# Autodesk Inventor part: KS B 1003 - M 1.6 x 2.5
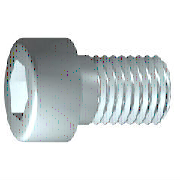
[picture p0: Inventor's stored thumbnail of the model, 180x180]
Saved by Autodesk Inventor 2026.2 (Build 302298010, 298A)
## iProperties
Created: 2025-01
Part Number: KS B 1003 - M 1.6 x 2.5
Material: 강철, 연강
Description: 6각머리 태핑 나사
Document SubType Name: Modeling
Standard: KS B 1003
Designer: khw
Standards Organization: KS
Language: ko-KR
Size Designation: M 1.6 x 2.5
Categories: <MemberInstance><Categories><Category DisplayName="조임쇠" InternalName="e4da775c-781d-43d5-af7c-5136215cf5a6" Mnemonic="FSTN"><Category DisplayName="볼트" InternalN
Density: 7.85 g/cm^3
Appearance: 반연마
IsCustomPart: 1
Author: khw
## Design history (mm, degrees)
workplane "Work Plane1"
fillet "Fillet2" dims "d30" = 0.1 (= R)
revolve "본체" stored, may be unused: angle "d10" = 90 deg
sketch "스케치2"
  geometry: L1 (0, -2.1)-(0, 2.1) reference; L2 (-2.1, 0)-(2.1, 0) reference; L3 (0.866, 0)-(0.433, -0.75); L4 (0.433, -0.75)-(-0.433, -0.75); L5 (-0.433, -0.75)-(-0.866, 0); L6 (-0.866, 0)-(-0.433, 0.75); L7 (-0.433, 0.75)-(0.433, 0.75); L8 (0.433, 0.75)-(0.866, 0); 2 further points
  constraints: 12 end point, 1 coincident, 1 horizontal alignment, 1 point on line, 12 other
extrude "슬롯" join sketch "스케치2" stored distance "d11" = 10; taper "d12" = 0 deg
body "Solid1"
fillet "모깎기1" dims "d17" = 0.16 (= RR)
feature "스레드" dims "d13" = 1.625 (= GEL), "d14" = 0
chamfer "모따기1" distance "d15" = 0.21471 (= -0.5 x SPD + 0.5 x GD); stored, may be unused: second distance "d16" = 0.21471 (= GUL), angle "d27" = 45 deg
sketch "스케치1"
  geometry: L1 (-0.4, 0)-(2.5, 0); L2 (2.5, 0)-(2.5, 0.8); L3 (2.5, 0.8)-(0.875, 0.8); L4 (0.875, 0.8)-(0.66, 0.8); L5 (0.66, 0.8)-(0, 0.8); L6 (0, 0.8)-(0, 1.5); L7 (0, 1.5)-(-1.6, 1.5); L8 (-1.6, 1.5)-(-1.6, 0.866); L9 (-1.6, 0.866)-(-0.9, 0.866); L10 (-0.9, 0.866)-(-0.4, 0); L11 (-2.42, 0)-(3.32, 0) reference; L12 (0, -0.3)-(0, 1.8) reference; L13 (0.875, 0.8)-(0, 0.8)
  constraints: 22 end point, 6 parallel, 2 collinear, 2 perpendicular, 1 horizontal, 1 point on line
  dimensions: "d1" = 1.625 distance from line of L3.end L2 (= GEL); "d2" = 0.21481 distance of L4.end L3.end (computed from GAL); "d3" = 1.6 distance between parallel lines of L8 L6 (= KOH); "d4" = 0.7 distance of L8.end L9.end (= INTI); "d5" = 60 deg angle of L10 L1; "d6" = 1.6 diameter of L3 L1 (= GD); "d7" = 1.6 diameter of L5 L1 (= BDM); "d8" = 1.73205 diameter of L9 L1 (= 1.1547 x SW); "d9" = 3 diameter of L7 L1 (= KOD); "d26" = 2.5 distance between parallel lines of L12 L2 (= NLG)
other parameters: "GD" = 1.6 (= NND) [user parameter; used in 2 equation terms], "NLG" = 2.5 [user parameter; used in 1 equation term], "GEL" = 1.625 [user parameter; used in 2 equation terms], "KOD" = 3 [user parameter; used in 1 equation term], "KOH" = 1.6 [user parameter; used in 1 equation term], "INTI" = 0.7 [user parameter; used in 1 equation term], "GAL" = 0.21471 (= 0.61345 x PTC) [user parameter; used in 1 equation term], "GUL" = 0.21471 (= 0.61345 x PTC) [user parameter; used in 1 equation term], "BDM" = 1.6 (= NND) [user parameter; used in 1 equation term], "SW" = 1.5 [user parameter; used in 2 equation terms], "RR" = 0.16 [user parameter; used in 1 equation term], "SPD" = 1.17059 (= NND - 1.2269 x PTC) [user parameter; used in 1 equation term], "d19" = 0, "d28" = 0, "d29" = 0, "R" = 0.1 [user parameter; used in 1 equation term], "PHH" = 0.1 [user parameter], "GD1" = 1.17059 (= THREADDIA - 1.2269 x PTC) [user parameter], "THREADDIA" = 1.6 [user parameter; used in 1 equation term], "FAWI" = 45 deg [user parameter], "TPU" = 28.57143 (computed from PTC) [user parameter], "PTC" = 0.35 [user parameter; used in 5 equation terms], "NND" = 1.6 [user parameter; used in 3 equation terms], "TOA" = 30 deg [user parameter], "E0" = 1.7325 (= 1.155 x SW) [user parameter]
